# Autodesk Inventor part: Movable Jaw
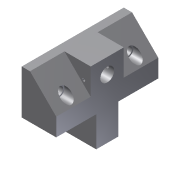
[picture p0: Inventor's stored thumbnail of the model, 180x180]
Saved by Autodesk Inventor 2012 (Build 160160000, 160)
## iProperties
Shininess: 77.0
Length Units: 11269
Angle Units: 11279
Time Units: 11290
Mass Units: 11283
Length Display Precision: 3
Angle Display Precision: 2
Created: 2002-02
Part Number: Movable Jaw
Document SubType Name: Modeling
Designer: ***
Density: 1 g/cm^3
Material: Default
Density: 0.0
Volumn: 0.0
Area: 0.0
PropertySet Name: Model Information
Control State: 0
Master: False
Checked Out: False
Author: ***
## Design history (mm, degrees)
sketch "Sketch2"
  geometry: L1 (2.39, 41.509)-(2.39, 9.509); L2 (2.39, 9.509)-(-22.61, 9.509); L3 (-22.61, 9.509)-(-22.61, 22.509); L4 (-22.61, 22.509)-(-3.61, 41.509); L5 (-3.61, 41.509)-(2.39, 41.509)
  constraints: 10 end point, 2 parallel, 1 perpendicular, 1 vertical
  dimensions: "d0" = 25 distance of L1.end L2.end; "d2" = 13 distance of L2.end L3.end; "d3" = 32 distance between parallel lines of L5 L2; "d4" = 6 distance of L4.end L1.start
extrude "Extrusion1" new body sketch "Sketch2" stored distance "d5" = 74; taper "d6" = 0 deg
sketch "Sketch3"
  geometry: L1 (-19, 25)-(11, 25); L2 (11, 25)-(11, 49); L3 (11, 49)-(-19, 49); L4 (-19, 49)-(-19, 25); L5 (0, 0)-(13, 0) reference; L6 (-19, 74)-(-19, 0) reference; L7 (11.924, 29)-(35, 29); L8 (35, 29)-(35, 45); L9 (35, 45)-(11.924, 45); L10 (11.924, 45)-(11.924, 29); L11 (13, 74)-(13, 0) reference
  constraints: 16 end point, 4 parallel, 2 horizontal, 2 perpendicular, 1 collinear
  dimensions: "d7" = 24 distance of L3.end L1.start; "d8" = 30 distance of L1.start L1.end; "d9" = 25 distance between parallel lines of L5 L1; "d10" = 16 distance of L7.end L8.end; "d11" = 4 distance between parallel lines of L3 L9; "d12" = 22 distance between parallel lines of L11 L8
extrude "Extrusion2" join sketch "Sketch3" distance "d13" = 25; taper "d14" = 0 deg
sketch "Sketch4"
  geometry: L1 (-19, -25)-(-19, -49) reference; L2 (-19, -49)-(0, -49) reference; 1 further point
  dimensions: "d15" = 11 distance from line of L1 point (-8, -37); "d16" = 12 distance from line of L2 point (-8, -37)
hole "Hole1" sketch "Sketch4" at (-8, -37) diameter "d17" = 10; stored, may be unused: countersink angle "d21" = 82 deg, drill point angle "d23" = 0 deg; dims "d18" = 6, "d19" = 4, "d20" = 2, "d22" = 13
sketch "Sketch5"
  geometry: L1 (-19, -49)-(-19, -74) reference; L2 (0, -74)-(13, -74) reference; 1 further point
  dimensions: "d24" = 14 distance from line of L1 point (-5, -62); "d25" = 12 distance from line of L2 point (-5, -62)
hole "Hole2" sketch "Sketch5" at (-5, -62) diameter "d26" = 6; stored, may be unused: countersink angle "d30" = 82 deg, drill point angle "d32" = 0 deg; dims "d27" = 6, "d28" = 8, "d29" = 10, "d31" = 13
mirror "Mirror1"
sketch "Sketch6"
  geometry: L1 (0, 19)-(0, 0) reference; 1 further point
  dimensions: "d33" = 5 distance from line of L1 point (-5, 8); "d34" = 11 vertical distance of L1.start point (-5, 8)
hole "Hole3" sketch "Sketch6" at (-5, 8) diameter "d35" = 2; stored, may be unused: countersink angle "d39" = 82 deg, drill point angle "d41" = 0 deg; dims "d36" = 6, "d37" = 8, "d38" = 10, "d40" = 13
body "Solid1"
